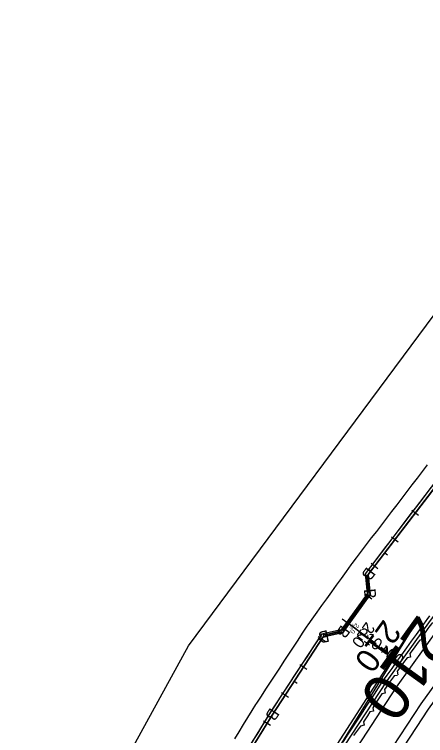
# Model space of a CAD drawing. Extents: x 1823824 to 1861612, y 706975 to 726130.
# Drawn here: x 1824542.7 to 1824788.8, y 711824 to 712255.1 of the extents above; entities that cross this region are included whole.
import ezdxf

# ---------------------------------------------------------------- set-up
doc = ezdxf.new("R2010")
doc.units = 0
for name, color, linetype in [('DR_X_Flood_Boundary', 7, 'Continuous'), ('GE_X_CL_10', 7, 'Continuous'), ('GE_X_CL_100', 7, 'Continuous'), ('GE_X_CL_20', 7, 'Continuous'), ('GE_X_CL_200', 7, 'Continuous'), ('GE_X_CL_50', 7, 'Continuous'), ('RW_X_Esmt_FL', 7, 'Continuous'), ('SC_Scratch1', 7, 'Continuous'), ('SC_Scratch3', 7, 'Continuous'), ('SC_Scratch5', 7, 'Continuous'), ('SC_Scratch6', 7, 'Continuous')]:
    doc.layers.add(name, color=color, linetype=linetype)

msp = doc.modelspace()

# ---------------------------------------------------------------- linework, layer by layer
at = {"layer": 'DR_X_Flood_Boundary'}
for p, q in [((1824802.7, 711983.32), (1824754.44, 711920.25)), ((1824754.44, 711920.25), (1824755.67, 711908.3)), ((1824755.67, 711908.3), (1824739.31, 711885.58)), ((1824727.6, 711882.96), (1824696.93, 711836.18)), ((1824739.31, 711885.58), (1824727.6, 711882.96)), ((1824696.93, 711836.18), (1824666.49, 711786.8))]:
    msp.add_line(p, q, dxfattribs=at)
at = {"layer": 'GE_X_CL_10'}
for p, q in [((1824764.36, 711933.21), (1824765.15, 711932.61)), ((1824743.01, 711890.72), (1824743.82, 711890.13)), ((1824710.24, 711856.47), (1824711.08, 711855.93))]:
    msp.add_line(p, q, dxfattribs=at)
at = {"layer": 'GE_X_CL_100'}
msp.add_line((1824743.01, 711890.72), (1824751.13, 711884.88), dxfattribs=at)
at = {"layer": 'GE_X_CL_20'}
for p, q in [((1824764.36, 711933.21), (1824765.95, 711932)), ((1824743.01, 711890.72), (1824744.63, 711889.55)), ((1824710.24, 711856.47), (1824711.91, 711855.38))]:
    msp.add_line(p, q, dxfattribs=at)
at = {"layer": 'GE_X_CL_200'}
msp.add_line((1824743.01, 711890.72), (1824759.24, 711879.03), dxfattribs=at)
at = {"layer": 'GE_X_CL_50'}
msp.add_line((1824743.01, 711890.72), (1824747.07, 711887.8), dxfattribs=at)
at = {"layer": 'RW_X_Esmt_FL'}
for p, q in [((1824646.86, 711877.55), (1824890.45, 712205.63)), ((1824561.76, 711722.66), (1824646.86, 711877.55))]:
    msp.add_line(p, q, dxfattribs=at)
at = {"layer": 'SC_Scratch1'}
for p, q in [((1824787.06, 711883.46), (1824787.4, 711881.38)), ((1824787.4, 711881.38), (1824785.32, 711881.04)), ((1824779.82, 711870.85), (1824777.74, 711870.51)), ((1824779.48, 711872.93), (1824779.82, 711870.85)), ((1824771.9, 711862.4), (1824772.24, 711860.32)), ((1824772.06, 711859.97), (1824769.99, 711859.62)), ((1824764.67, 711849.39), (1824762.61, 711848.95)), ((1824764.23, 711851.45), (1824764.67, 711849.39)), ((1824757.16, 711840.57), (1824757.59, 711838.51)), ((1824757.59, 711838.51), (1824755.53, 711838.07)), ((1824751.67, 711832.14), (1824752.1, 711830.13)), ((1824752, 711830.13), (1824749.81, 711829.67))]:
    msp.add_line(p, q, dxfattribs=at)
for points in [[(1825105.72, 712238.1), (1825041.58, 712175.28), (1825012.05, 712142.98), (1824928.03, 712058.8), (1824867.42, 711988.62), (1824838.82, 711954.42), (1824791.58, 711892.69), (1824765.73, 711856.76), (1824735.96, 711811.35), (1824706.1, 711762.93), (1824677.47, 711714.29), (1824651.68, 711665.89), (1824630.67, 711625.89), (1824564.54, 711490.46), (1824542.7, 711439.44)], [(1825110.13, 712232.99), (1825046.42, 712170.6), (1825016.92, 712138.33), (1824932.97, 712054.22), (1824872.55, 711984.27), (1824844.08, 711950.22), (1824796.99, 711888.68), (1824771.28, 711852.95), (1824741.64, 711807.74), (1824711.87, 711759.46), (1824683.34, 711710.99), (1824657.63, 711662.75), (1824636.68, 711622.85), (1824570.66, 711487.65), (1824551.08, 711441.92)], [(1825121.76, 712219.53), (1825059.19, 712158.26), (1825029.76, 712126.06), (1824945.98, 712042.13), (1824886.07, 711972.77), (1824857.94, 711939.13), (1824811.24, 711878.1), (1824785.91, 711842.89), (1824756.62, 711798.22), (1824727.07, 711750.3), (1824698.83, 711702.31), (1824673.32, 711654.44), (1824652.51, 711614.83), (1824615.99, 711540.02)], [(1825125.32, 712215.32), (1825063.14, 712154.44), (1825033.74, 712122.26), (1824950.02, 712038.39), (1824890.27, 711969.21), (1824862.23, 711935.69), (1824815.66, 711874.82), (1824790.44, 711839.78), (1824761.26, 711795.26), (1824731.78, 711747.46), (1824703.63, 711699.63), (1824678.18, 711651.87), (1824657.42, 711612.34), (1824626.24, 711548.48)], [(1824789.77, 711985.77), (1824786.74, 711981.8), (1824783.7, 711977.83), (1824780.66, 711973.86), (1824777.62, 711969.89), (1824774.58, 711965.92), (1824771.55, 711961.95), (1824768.51, 711957.97), (1824765.47, 711954), (1824762.43, 711950.03), (1824759.39, 711946.06), (1824756.35, 711942.09), (1824753.32, 711938.12), (1824750.28, 711934.15), (1824747.24, 711930.18), (1824744.67, 711926.82), (1824744.13, 711926.08), (1824741.21, 711922.02), (1824738.29, 711917.96), (1824735.37, 711913.9), (1824732.45, 711909.85), (1824729.52, 711905.79), (1824726.6, 711901.73), (1824723.68, 711897.67), (1824720.76, 711893.62), (1824718.34, 711890.26), (1824717.75, 711889.36), (1824715, 711885.17), (1824712.26, 711880.99), (1824709.52, 711876.81), (1824706.78, 711872.63), (1824704.04, 711868.45), (1824701.3, 711864.27), (1824698.56, 711860.09)], [(1824801.74, 711984.95), (1824801.66, 711984.85), (1824800.75, 711983.67), (1824797.72, 711979.7), (1824794.68, 711975.72), (1824791.64, 711971.75), (1824788.6, 711967.78), (1824785.56, 711963.81), (1824782.53, 711959.84), (1824779.49, 711955.87), (1824776.45, 711951.9), (1824773.41, 711947.93), (1824770.37, 711943.96), (1824767.33, 711939.99), (1824764.3, 711936.01), (1824761.26, 711932.04), (1824758.22, 711928.07), (1824755.18, 711924.1), (1824752.63, 711920.76)], [(1824572.41, 711565.5), (1824785.18, 711894.95), (1824731.76, 711808.36)], [(1824791.23, 711895.52), (1824789.6, 711893.38), (1824789.03, 711892.56), (1824786.1, 711888.49), (1824783.18, 711884.43), (1824780.26, 711880.37), (1824777.34, 711876.32), (1824774.42, 711872.26), (1824771.5, 711868.2), (1824768.58, 711864.14), (1824765.66, 711860.08), (1824764.08, 711857.89), (1824761.13, 711853.4), (1824758.39, 711849.22), (1824755.65, 711845.04), (1824752.91, 711840.85), (1824750.17, 711836.67), (1824747.43, 711832.49), (1824744.68, 711828.31), (1824741.94, 711824.13), (1824739.2, 711819.95)], [(1824792.97, 711891.53), (1824792.44, 711890.84), (1824790.81, 711888.7), (1824790.24, 711887.88), (1824787.31, 711883.81), (1824787.06, 711883.46)], [(1824726.53, 711884.51), (1824726.46, 711884.42), (1824726.11, 711883.87), (1824723.37, 711879.69), (1824720.63, 711875.51), (1824717.88, 711871.33), (1824715.14, 711867.15), (1824712.4, 711862.97), (1824709.66, 711858.78), (1824706.92, 711854.6), (1824704.18, 711850.42), (1824701.44, 711846.24), (1824698.7, 711842.06), (1824695.95, 711837.88), (1824695.39, 711837.01), (1824693.38, 711833.75), (1824690.76, 711829.5), (1824688.13, 711825.24), (1824685.51, 711820.99), (1824682.88, 711816.73)], [(1824785.32, 711881.04), (1824784.39, 711879.75), (1824781.47, 711875.69), (1824779.48, 711872.93)], [(1824777.74, 711870.51), (1824775.63, 711867.58), (1824772.71, 711863.52), (1824771.9, 711862.4)], [(1824698.56, 711860.09), (1824695.82, 711855.9), (1824693.07, 711851.72), (1824690.33, 711847.54), (1824687.59, 711843.36), (1824687.02, 711842.49), (1824684.87, 711839), (1824682.24, 711834.75), (1824679.62, 711830.49), (1824677, 711826.23), (1824674.37, 711821.98)], [(1824769.99, 711859.62), (1824769.62, 711859.11), (1824766.71, 711855.04), (1824765.14, 711852.84), (1824764.23, 711851.45)], [(1824762.61, 711848.95), (1824762.21, 711848.34), (1824759.48, 711844.14), (1824757.16, 711840.57)], [(1824755.53, 711838.07), (1824754.03, 711835.76), (1824751.67, 711832.14)], [(1824749.81, 711829.67), (1824745.71, 711823.95)]]:
    msp.add_lwpolyline(points, dxfattribs=at)
at = {"layer": 'SC_Scratch3'}
for p, q in [((1824755.96, 711922.24), (1824754.57, 711923.3)), ((1824754.12, 711919.74), (1824753.12, 711919.64)), ((1824753.12, 711919.64), (1824753.22, 711918.65)), ((1824753.22, 711918.65), (1824754.22, 711918.75)), ((1824754.47, 711910.19), (1824753.6, 711918.69)), ((1824754.72, 711910.21), (1824753.84, 711918.71)), ((1824754.22, 711918.75), (1824754.12, 711919.74)), ((1824753.97, 711908.29), (1824753.39, 711907.48)), ((1824754.78, 711907.71), (1824753.97, 711908.29)), ((1824755.09, 711910.25), (1824754.1, 711910.15)), ((1824754.1, 711910.15), (1824754.2, 711909.16)), ((1824754.2, 711909.16), (1824755.2, 711909.26)), ((1824755.2, 711909.26), (1824755.09, 711910.25)), ((1824753.69, 711907.26), (1824739.67, 711887.79)), ((1824753.89, 711907.12), (1824739.87, 711887.64)), ((1824753.39, 711907.48), (1824754.2, 711906.9)), ((1824754.2, 711906.9), (1824754.78, 711907.71)), ((1824749.17, 711900.56), (1824748.97, 711900.7)), ((1824749.27, 711900.69), (1824749.06, 711900.84)), ((1824744.5, 711894.06), (1824744.29, 711894.21)), ((1824744.59, 711894.2), (1824744.39, 711894.35)), ((1824737.06, 711886.48), (1824738.03, 711886.7)), ((1824737.28, 711885.51), (1824737.06, 711886.48)), ((1824738.03, 711886.7), (1824738.25, 711885.73)), ((1824738.78, 711887.19), (1824739.36, 711888.01)), ((1824739.59, 711886.61), (1824738.78, 711887.19)), ((1824739.36, 711888.01), (1824740.17, 711887.42)), ((1824740.17, 711887.42), (1824739.59, 711886.61)), ((1824727.75, 711884.4), (1824728.72, 711884.62)), ((1824727.96, 711883.43), (1824727.75, 711884.4)), ((1824728.94, 711883.64), (1824727.96, 711883.43)), ((1824728.72, 711884.62), (1824728.94, 711883.64)), ((1824737.14, 711886.12), (1824728.8, 711884.25)), ((1824737.19, 711885.87), (1824728.86, 711884.01)), ((1824738.25, 711885.73), (1824737.28, 711885.51)), ((1824726.23, 711880.87), (1824724.77, 711881.83))]:
    msp.add_line(p, q, dxfattribs=at)
for points in [[(1825072.21, 712272.45), (1825008.3, 712207.43), (1825011.73, 712194.9), (1824990.64, 712173.59), (1824978.07, 712176.88), (1824892.84, 712091.49), (1824830.41, 712019.21), (1824830.77, 712007.17), (1824813.65, 711986.72), (1824801.74, 711984.95), (1824752.63, 711920.76), (1824753.86, 711908.78), (1824738.28, 711887.14), (1824726.53, 711884.51), (1824695.45, 711837.1), (1824665, 711787.73)], [(1824666.49, 711786.8), (1824696.93, 711836.18), (1824727.6, 711882.96), (1824739.31, 711885.58), (1824755.67, 711908.3), (1824754.44, 711920.25), (1824802.7, 711983.32), (1824814.57, 711985.09), (1824832.54, 712006.56), (1824832.18, 712018.58), (1824894.12, 712090.29), (1824978.6, 712174.93), (1824991.17, 712171.64), (1825013.68, 712194.38), (1825010.26, 712206.92), (1825073.72, 712271.49)]]:
    msp.add_lwpolyline(points, dxfattribs=at)
at = {"layer": 'SC_Scratch5'}
for points in [[(1824784.57, 711955.52), (1824780.6, 711958.56)], [(1824772.42, 711939.64), (1824768.45, 711942.67)], [(1824760.27, 711923.75), (1824756.3, 711926.79)], [(1824756.73, 711905.49), (1824752.67, 711908.41)], [(1824747.07, 711887.8), (1824738.95, 711893.64)], [(1824728.78, 711880.19), (1824724.6, 711882.93)], [(1824717.81, 711863.47), (1824713.63, 711866.21)], [(1824706.85, 711846.74), (1824702.67, 711849.48)], [(1824696.05, 711829.99), (1824691.8, 711832.61)]]:
    msp.add_lwpolyline(points, dxfattribs=at)

# ---------------------------------------------------------------- texts
at = {"layer": 'GE_X_CL_10'}
msp.add_text('210', height=1.4, rotation=234.2454, dxfattribs=at).set_placement((1824745.09, 711891.05))
at = {"layer": 'GE_X_CL_100'}
msp.add_text('210', height=14, rotation=234.2454, dxfattribs=at).set_placement((1824763.84, 711893.98))
at = {"layer": 'GE_X_CL_20'}
msp.add_text('210', height=2.8, rotation=234.2454, dxfattribs=at).set_placement((1824747.18, 711891.37))
at = {"layer": 'GE_X_CL_200'}
msp.add_text('210', height=28, rotation=234.2454, dxfattribs=at).set_placement((1824784.68, 711897.25))
at = {"layer": 'GE_X_CL_50'}
msp.add_text('210', height=7, rotation=234.2454, dxfattribs=at).set_placement((1824753.43, 711892.35))
at = {"layer": 'SC_Scratch5'}
msp.add_text('210+00', height=7, rotation=324.2454, dxfattribs=at).set_placement((1824747.05, 711883.5))
at = {"layer": 'SC_Scratch6'}
for rotation, p in [(232.5796, (1824753.79, 711925.16)), (275.8767, (1824751.83, 711911.43)), (192.6091, (1824730.25, 711887.14)), (234.2454, (1824738.51, 711890.46)), (236.7531, (1824695.92, 711841.02))]:
    msp.add_text('B', height=7, rotation=rotation, dxfattribs=at).set_placement(p)

doc.saveas('drawing.dxf')
